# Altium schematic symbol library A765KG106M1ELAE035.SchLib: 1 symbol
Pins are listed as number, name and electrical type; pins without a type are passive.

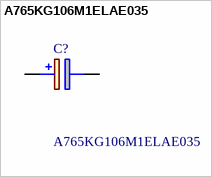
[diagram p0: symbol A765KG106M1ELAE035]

## A765KG106M1ELAE035
designator C?
A765, Aluminum, Polymer Aluminum, 10 uF, 20%, 25 VDC, -55/+105C, 105C, -55C, 105C, 2,000 Hrs, 35 mOhms, 125 uA, 8mm, 7mm; Manufacturer_Name: KEMET; Geometry.Height: 7.3mm
footprint CAPAE830X730N
pins: 1 +, 2 -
